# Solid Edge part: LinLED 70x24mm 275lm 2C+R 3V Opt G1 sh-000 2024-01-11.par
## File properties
Author: robert.pupel
Template: iso metric part.par
Last saved by: robert.pupel
Revision: 3
Application: Solid Edge
Gęstość: 0.000 kg/m^3
Dokładność: 0.990
Username: robert.pupel
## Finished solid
Body 1: solid body, 1192 faces, 3016 edges, 1892 vertices.
  Faces by surface: plane 595, cylinder 281, torus 128, cone 100, spline 52, sphere 32, swept 4
  Edges by curve: line 1638, curve on surface 752, circle 326, spline 168, ellipse 132
Bounding box of the edges (mm; curved faces can reach further): 69.600 x 4.450 x 24.000, from (-34.8, -3.45, -12) to (34.8, 1, 12).
Cylindrical faces by radius (mm): R0.2 x92, R0.2169 x12, R0.25 x26, R0.3373 x12, R0.4 x16, R0.4006 x4, R0.4008 x4, R0.525 x4, R0.6 x40, R1 x24, R1.1 x8, R1.1989 x4, R1.199 x4, R1.2 x20, R1.5309 x2, R1.5312 x2, R1.7414 x2, R1.7423 x2, R2.15 x3
Conical faces (half-angle, radius in mm at the cone's reference point): 0.398 deg R1.1964 x4, 0.4493 deg R1.1964 x4, 0.4746 deg R1.1948 x4, 0.4758 deg R1.1948 x4, 0.5 deg R0.5056 x8, 0.5 deg R1.0082 x8, 1 deg R0.5511 x4, 10 deg R0.2132 x8, 10 deg R0.4132 x8, 16.0099 deg R1.1053 x4, 16.1249 deg R1.1279 x4, 18.8604 deg R1.0669 x8, 19.5041 deg R0.5138 x4, 19.8244 deg R0.5099 x4, 27.363 deg R0.6214 x4, 40.6434 deg R0.5161 x4, 43.3309 deg R0.4892 x4, 45 deg R0.575 x4, 45 deg R0.625 x8
Toroidal faces (ring radius, tube radius in mm): R0.0958 r0.3997 x8, R0.1076 r0.4 x4, R0.1101 r0.4001 x4, R0.1217 r0.4 x4, R0.1234 r0.4 x4, R0.1626 r0.228 x4, R0.1634 r0.2287 x4, R0.3287 r0.2001 x4, R0.3684 r0.2151 x4, R0.3703 r0.4 x4, R0.3818 r0.2 x8, R0.4166 r0.3983 x4, R0.5981 r0.197 x4, R0.5982 r0.197 x4, R0.6009 r0.3968 x4, R0.6009 r0.3969 x4, R0.6227 r0.2 x4, R0.6235 r0.2 x4, R0.8 r0.2 x8, R0.8522 r0.3 x4, R0.9002 r0.2 x4, R0.9018 r0.2 x4, R0.9197 r0.223 x4, R0.9365 r0.2 x4, R0.9663 r0.2263 x4, R0.9665 r0.2263 x4, R1.429 r1.2 x4, R1.8741 r0.2175 x4, R1.9007 r0.2 x4
Spherical faces by radius (mm): R0.2 x24, R0.6 x8
Planar faces by outward normal: +x 62, +y 17, +z 64, -x 62, -y 89, -z 65, oblique 236
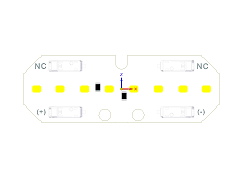
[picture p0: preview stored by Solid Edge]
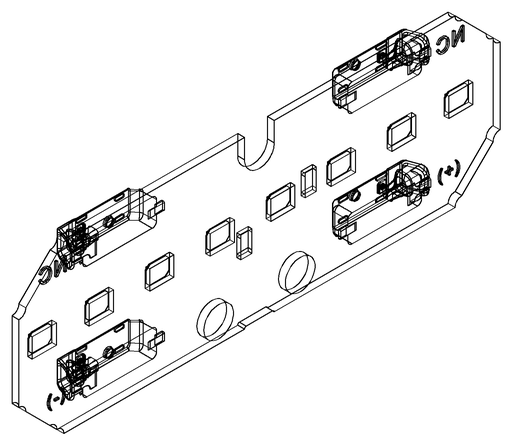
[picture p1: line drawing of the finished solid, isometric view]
